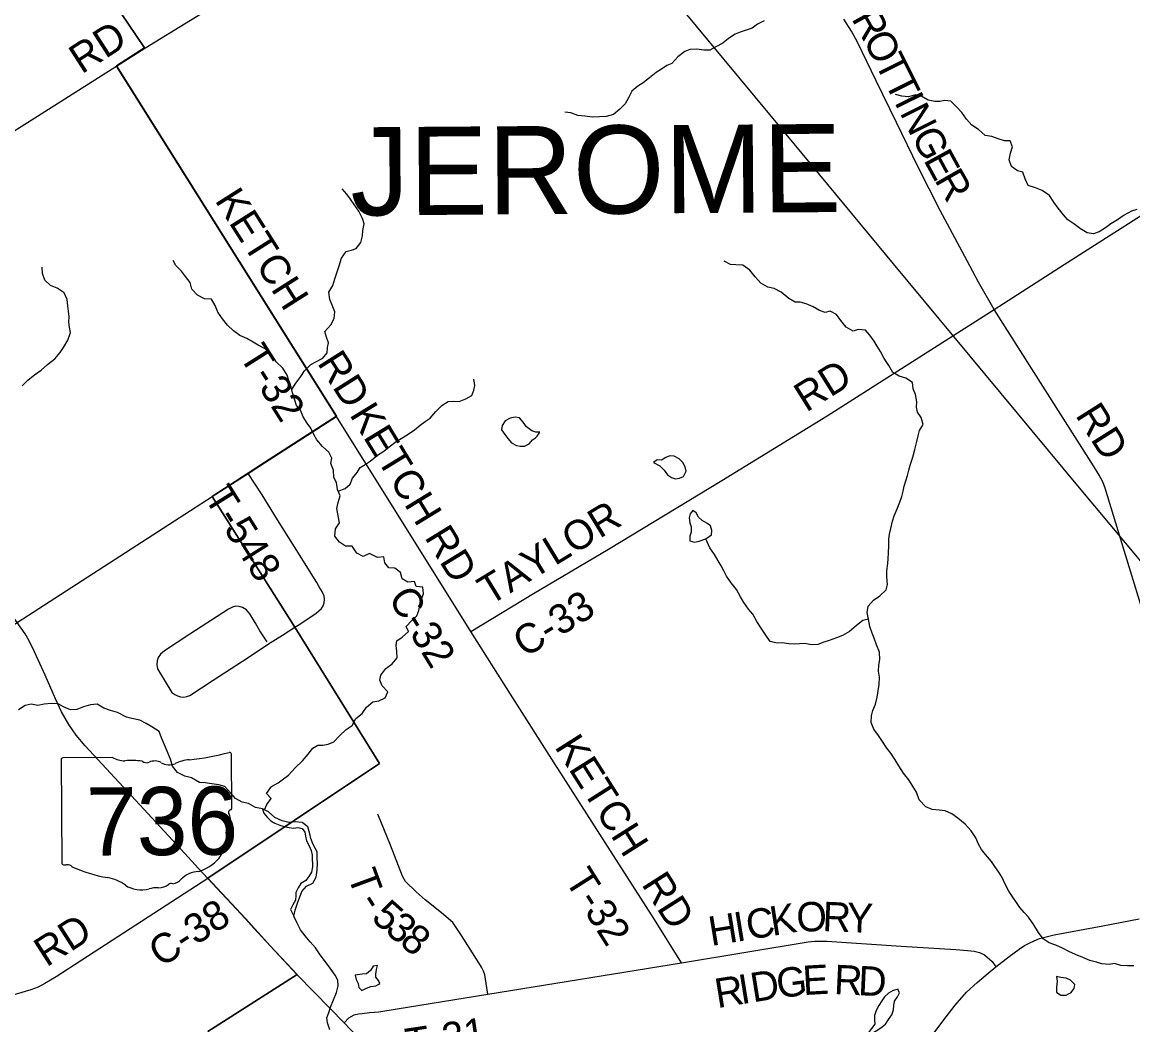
# Model space of a CAD drawing. Extents: x 114843 to 284848, y 317643 to 566895.
# Drawn here: x 122583 to 133928, y 449771 to 460005 of the extents above; entities that cross this region are included whole.
import ezdxf

# ---------------------------------------------------------------- set-up
doc = ezdxf.new("R2010")
doc.units = 0
for name, color, linetype in [('GM_X_County_Road', 7, 'Continuous'), ('GM_X_County_Road_Text', 7, 'Continuous'), ('GM_X_Minor_Lake', 7, 'Continuous'), ('GM_X_Minor_River', 7, 'Continuous'), ('GM_X_Rail_Line', 7, 'Continuous'), ('GM_X_State_Location', 7, 'Continuous'), ('GM_X_State_Route', 7, 'Continuous'), ('GM_X_State_Shield', 7, 'Continuous'), ('GM_X_Township', 7, 'Continuous'), ('GM_X_Township_Road', 7, 'Continuous'), ('GM_X_Township_Road_Text', 7, 'Continuous'), ('GM_X_Township_Text', 7, 'Continuous'), ('GM_X_US_Route', 7, 'Continuous')]:
    doc.layers.add(name, color=color, linetype=linetype)

msp = doc.modelspace()

# ---------------------------------------------------------------- linework, layer by layer
at = {"layer": 'GM_X_County_Road'}
for p, q in [((119922, 457268), (123503, 459530)), ((127165, 453787), (125795, 455981))]:
    msp.add_line(p, q, dxfattribs=at)
for points in [[(123503, 459530), (123547, 459558), (123835, 459740), (124769, 460317), (125852, 460988), (126885, 461624), (127403, 461928), (128041, 462305), (128800, 462760), (129060, 462921)], [(127165, 453787), (127806, 454172), (128572, 454626), (129729, 455328), (130805, 455988), (132510, 457074), (133226, 457531), (134315, 458226), (134761, 458512), (135424, 458946), (136182, 459448), (137071, 460040)], [(134087, 453804), (133840, 454613), (133647, 455248), (133620, 455313), (133584, 455383), (133526, 455477), (133168, 456038), (132510, 457074), (132352, 457352), (132237, 457571), (131960, 458084), (131737, 458524), (131513, 458982), (131306, 459407), (131114, 459802), (131053, 459913), (130977, 460037)], [(116865, 450191), (119055, 451622), (120275, 452411), (121363, 453112), (122533, 453877), (124525, 455162), (124893, 455400), (125060, 455508), (125795, 455981)], [(124481, 451264), (123193, 450430), (122929, 450259), (122814, 450192), (122745, 450154), (122672, 450126), (122520, 450083), (122291, 450023), (122223, 450000), (122163, 449980), (122102, 449952), (122051, 449925), (121544, 449630)]]:
    msp.add_lwpolyline(points, dxfattribs=at)
at = {"layer": 'GM_X_Minor_Lake'}
for points in [[(127826, 455764), (127844, 455779), (127872, 455821), (127830, 455821), (127788, 455833), (127736, 455875), (127702, 455923), (127662, 455965), (127620, 455975), (127568, 455963), (127518, 455937), (127486, 455887), (127478, 455845)], [(127478, 455845), (127512, 455797), (127545, 455757), (127581, 455713), (127633, 455683), (127671, 455677), (127713, 455677), (127761, 455701), (127795, 455741), (127826, 455764)], [(129349, 455387), (129365, 455422), (129355, 455466), (129332, 455512), (129294, 455547), (129242, 455577), (129200, 455579), (129158, 455561), (129115, 455535), (129071, 455537), (129033, 455510)], [(129033, 455510), (129097, 455477), (129141, 455431), (129175, 455384), (129215, 455356), (129255, 455344), (129299, 455352), (129339, 455368), (129349, 455387)], [(129566, 454732), (129626, 454773), (129628, 454817), (129613, 454865), (129575, 454893), (129529, 454919), (129491, 454953), (129469, 454997), (129435, 455022), (129419, 455003)], [(129419, 455003), (129407, 454988), (129395, 454947), (129403, 454895), (129416, 454855), (129416, 454799), (129404, 454757), (129404, 454711), (129450, 454699), (129500, 454709), (129566, 454732)], [(125037, 451976), (125050, 451930), (125086, 451890), (125122, 451853), (125164, 451829), (125216, 451809), (125260, 451795), (125310, 451783), (125356, 451777), (125402, 451783), (125442, 451773), (125472, 451737), (125478, 451695), (125488, 451649), (125514, 451597), (125536, 451550), (125544, 451502), (125546, 451456), (125550, 451416), (125550, 451382), (125538, 451328), (125510, 451284), (125479, 451244), (125431, 451212), (125403, 451170), (125379, 451120), (125377, 451090), (125375, 451044), (125349, 450996), (125325, 450948), (125357, 450878)], [(125357, 450878), (125371, 450942), (125395, 451012), (125417, 451068), (125439, 451130), (125489, 451186), (125551, 451216), (125586, 451276), (125598, 451348), (125600, 451420), (125596, 451472), (125596, 451536), (125556, 451611), (125532, 451671), (125522, 451721), (125502, 451791), (125442, 451835), (125372, 451841), (125308, 451835), (125238, 451851), (125164, 451887), (125099, 451946), (125037, 451976)], [(126219, 450183), (126236, 450191), (126224, 450221), (126194, 450257), (126194, 450287), (126204, 450334), (126212, 450374), (126168, 450370), (126142, 450324), (126100, 450292), (126056, 450288), (125986, 450276)], [(125986, 450276), (125996, 450234), (126014, 450192), (126022, 450151), (126054, 450119), (126100, 450145), (126146, 450161), (126194, 450169), (126219, 450183)], [(133150, 450265), (133156, 450215), (133148, 450153), (133150, 450105), (133192, 450074), (133248, 450072), (133277, 450089)], [(133277, 450089), (133294, 450098), (133330, 450140), (133336, 450182), (133290, 450225), (133246, 450245), (133194, 450253), (133150, 450265)], [(131535, 450121), (131531, 450133), (131479, 450119), (131431, 450093), (131393, 450055), (131365, 450015), (131333, 449967), (131305, 449917), (131289, 449866), (131291, 449822), (131293, 449776), (131259, 449734), (131228, 449692), (131210, 449650)], [(131210, 449650), (131264, 449684), (131305, 449710), (131353, 449738), (131401, 449778), (131433, 449824), (131467, 449872), (131485, 449924), (131487, 449968), (131493, 450010), (131523, 450056), (131543, 450097), (131535, 450121)]]:
    msp.add_lwpolyline(points, dxfattribs=at)
at = {"layer": 'GM_X_Minor_River'}
for points in [[(130163, 460019), (130093, 459987), (130041, 459945), (129987, 459929), (129917, 459905), (129865, 459885), (129799, 459839), (129739, 459791), (129669, 459753), (129607, 459719), (129545, 459719), (129475, 459729), (129403, 459727), (129351, 459707), (129282, 459653), (129218, 459585), (129168, 459565), (129114, 459527), (129060, 459493), (128990, 459439), (128926, 459385), (128872, 459353), (128810, 459301), (128776, 459233), (128741, 459173), (128689, 459119), (128623, 459063), (128547, 459043), (128479, 459041), (128405, 459037), (128329, 459047), (128259, 459053), (128189, 459082), (128125, 459088)], [(133969, 458093), (133915, 458077), (133841, 458035), (133773, 457987), (133705, 457947), (133649, 457907), (133583, 457865), (133528, 457845), (133462, 457855), (133393, 457897), (133327, 457946), (133263, 457988), (133219, 458040), (133167, 458106), (133121, 458170), (133077, 458236), (133003, 458289), (132933, 458313), (132859, 458339), (132829, 458407), (132803, 458475), (132749, 458487), (132689, 458531), (132664, 458599), (132678, 458670), (132700, 458734), (132674, 458794), (132618, 458796), (132554, 458816), (132488, 458838), (132420, 458850), (132352, 458910), (132284, 458956), (132230, 459017), (132182, 459085), (132132, 459139), (132070, 459201), (132008, 459205), (131958, 459195), (131906, 459197), (131838, 459209), (131774, 459248), (131708, 459264), (131638, 459244), (131568, 459252), (131504, 459266)], [(125337, 456256), (125378, 456321), (125428, 456389), (125468, 456447), (125530, 456511), (125584, 456539), (125654, 456575), (125700, 456631), (125701, 456683), (125711, 456733), (125687, 456799), (125675, 456849), (125737, 456915), (125769, 456981), (125777, 457049), (125749, 457117), (125725, 457176), (125716, 457250), (125758, 457316), (125778, 457386), (125796, 457448), (125820, 457518), (125844, 457596), (125894, 457664), (125946, 457678), (125996, 457694), (126044, 457758), (126059, 457826), (126063, 457878), (126077, 457946), (126059, 458002), (126021, 458077), (125973, 458145), (125937, 458199), (125901, 458249), (125853, 458303)], [(124553, 457113), (124517, 457177), (124445, 457181), (124373, 457219), (124315, 457279), (124299, 457348), (124251, 457408), (124210, 457464), (124154, 457522), (124124, 457572)], [(131243, 453837), (131227, 453911), (131214, 453980), (131224, 454044), (131278, 454104), (131344, 454150), (131408, 454212), (131422, 454264), (131416, 454342), (131414, 454404), (131426, 454480), (131430, 454530), (131433, 454586), (131435, 454664), (131435, 454727), (131443, 454779), (131457, 454837), (131473, 454913), (131491, 454967), (131521, 455037), (131547, 455105), (131570, 455165), (131582, 455219), (131592, 455269), (131608, 455323), (131628, 455379), (131640, 455432), (131658, 455494), (131682, 455564), (131702, 455644), (131720, 455712), (131737, 455784), (131749, 455836), (131785, 455900), (131765, 455970), (131727, 456024), (131717, 456075), (131721, 456131), (131709, 456205), (131683, 456263), (131677, 456329), (131610, 456373), (131540, 456391), (131476, 456431), (131436, 456500), (131388, 456572), (131352, 456644), (131316, 456698), (131286, 456748), (131240, 456810), (131196, 456860), (131122, 456867), (131072, 456853), (131000, 456893), (130946, 456959), (130902, 457021), (130836, 457055), (130784, 457043), (130728, 457063), (130662, 457099), (130593, 457132), (130529, 457146), (130479, 457146), (130413, 457184), (130335, 457248), (130265, 457286), (130201, 457300), (130127, 457343), (130071, 457405), (130015, 457473), (129945, 457525), (129873, 457529), (129819, 457533), (129755, 457565)], [(122583, 456292), (122645, 456356), (122709, 456404), (122778, 456454), (122842, 456512), (122918, 456568), (122970, 456632), (123004, 456686), (123048, 456760), (123076, 456838), (123068, 456892), (123060, 456945), (123062, 456997), (123057, 457055), (123049, 457111), (123041, 457175), (123011, 457243), (122939, 457291), (122871, 457317), (122813, 457371), (122791, 457440), (122787, 457504)], [(125059, 451965), (125081, 452018), (125127, 452080), (125079, 452132), (125131, 452202), (125197, 452240), (125251, 452282), (125305, 452320), (125373, 452394), (125445, 452466), (125506, 452532), (125552, 452594), (125604, 452626), (125654, 452626), (125710, 452634), (125766, 452658), (125824, 452720), (125892, 452784), (125954, 452826), (125992, 452896), (126056, 452950), (126101, 453012), (126165, 453068), (126227, 453078), (126291, 453108), (126319, 453170), (126259, 453232), (126237, 453287), (126245, 453339), (126297, 453409), (126361, 453457), (126413, 453517), (126410, 453585), (126404, 453641), (126410, 453691), (126464, 453729), (126530, 453785), (126504, 453835), (126560, 453895), (126616, 453945), (126634, 453999), (126646, 454053), (126654, 454103), (126683, 454171), (126677, 454238), (126609, 454244), (126589, 454296), (126523, 454288), (126465, 454324), (126447, 454388), (126391, 454432), (126327, 454436), (126287, 454488), (126279, 454547), (126211, 454541), (126131, 454581), (126067, 454551), (126001, 454585), (125953, 454655), (125887, 454657), (125823, 454699), (125777, 454760), (125783, 454832), (125826, 454896), (125810, 454966), (125798, 455040), (125810, 455102), (125830, 455170), (125804, 455236), (125794, 455306), (125768, 455357), (125764, 455431), (125737, 455499), (125747, 455555), (125715, 455615), (125651, 455673), (125593, 455743), (125563, 455796), (125531, 455862), (125495, 455912), (125455, 455978), (125425, 456044), (125385, 456094), (125364, 456158), (125346, 456223), (125332, 456279), (125308, 456347), (125290, 456401), (125246, 456475), (125178, 456539), (125134, 456609), (125064, 456670), (124994, 456708), (124942, 456738), (124877, 456776), (124805, 456808), (124741, 456854), (124679, 456912), (124629, 456977), (124583, 457045), (124553, 457113)], [(125811, 455218), (125882, 455244), (125934, 455288), (125956, 455352), (126004, 455408), (126035, 455460), (126087, 455490), (126137, 455526), (126211, 455584), (126279, 455628), (126331, 455670), (126403, 455726), (126453, 455756), (126515, 455792), (126589, 455844), (126647, 455892), (126700, 455928), (126750, 455962), (126810, 456032), (126870, 456094), (126936, 456132), (126986, 456138), (127048, 456132), (127114, 456160), (127176, 456196), (127198, 456248), (127206, 456298), (127196, 456362)], [(131227, 453911), (131171, 453897), (131105, 453847), (131035, 453785), (130963, 453743), (130901, 453722), (130827, 453694), (130773, 453678), (130711, 453654), (130645, 453650), (130579, 453664), (130523, 453660), (130471, 453656), (130415, 453660), (130345, 453670), (130295, 453668), (130223, 453682), (130179, 453748), (130131, 453819), (130087, 453889), (130047, 453961), (130003, 454013), (129955, 454081), (129919, 454139), (129880, 454214), (129824, 454282), (129776, 454350), (129752, 454404), (129724, 454456), (129692, 454508), (129656, 454571), (129608, 454639), (129566, 454732)], [(133940, 450372), (133872, 450372), (133806, 450376), (133742, 450396), (133688, 450386), (133612, 450394), (133556, 450411), (133488, 450427), (133416, 450459), (133342, 450489), (133274, 450517), (133210, 450551), (133142, 450583), (133074, 450606), (133013, 450648), (132965, 450712), (132917, 450792), (132863, 450868), (132817, 450918), (132775, 450968), (132739, 451019), (132703, 451073), (132661, 451133), (132619, 451213), (132593, 451273), (132558, 451329), (132518, 451388), (132486, 451438), (132422, 451510), (132384, 451560), (132352, 451616), (132324, 451678), (132278, 451750), (132214, 451817), (132140, 451879), (132078, 451925), (132012, 451953), (131950, 451961), (131880, 451969), (131812, 451995), (131746, 452068), (131717, 452144), (131685, 452200), (131639, 452270), (131587, 452338), (131537, 452413), (131499, 452475), (131455, 452545), (131417, 452595), (131371, 452663), (131329, 452725), (131284, 452789), (131254, 452856), (131260, 452926), (131274, 452980), (131298, 453042), (131318, 453116), (131326, 453178), (131336, 453246), (131340, 453320), (131331, 453380), (131333, 453441), (131343, 453501), (131339, 453575), (131309, 453649), (131287, 453717), (131265, 453769), (131243, 453837)], [(123004, 453018), (122952, 453046), (122878, 453052), (122808, 453043), (122742, 453029), (122674, 453043), (122612, 453031), (122546, 452985)], [(125727, 449719), (125701, 449789), (125695, 449841), (125715, 449897), (125733, 449949), (125764, 450024), (125794, 450100), (125810, 450168), (125808, 450226), (125780, 450276), (125730, 450348), (125682, 450414), (125626, 450483), (125578, 450555), (125524, 450617), (125473, 450677), (125425, 450741), (125387, 450813), (125357, 450878), (125371, 450942), (125395, 451012), (125417, 451068), (125439, 451130), (125489, 451186), (125551, 451216), (125586, 451276), (125598, 451348), (125600, 451420), (125596, 451472), (125596, 451536), (125556, 451611), (125532, 451671), (125522, 451721), (125502, 451791), (125442, 451835), (125372, 451841), (125308, 451835), (125238, 451851), (125164, 451887), (125099, 451946), (125037, 451976), (124965, 451988), (124895, 452030), (124831, 452042), (124763, 452080), (124715, 452134), (124653, 452203), (124591, 452219), (124521, 452231), (124451, 452239), (124393, 452245), (124313, 452291), (124245, 452307), (124171, 452346), (124117, 452410), (124097, 452482), (124037, 452630), (124006, 452700), (123984, 452766), (123908, 452813), (123850, 452847), (123784, 452881), (123704, 452897), (123650, 452911), (123558, 452959), (123486, 452978), (123416, 453002), (123350, 453044), (123280, 453038), (123210, 453018), (123142, 452988), (123078, 452986), (123004, 453018)]]:
    msp.add_lwpolyline(points, dxfattribs=at)
at = {"layer": 'GM_X_Rail_Line'}
msp.add_lwpolyline([(138183, 449466), (136987, 450906), (136046, 452039), (135244, 453008), (134166, 454316), (133384, 455251), (132101, 456798), (131484, 457539), (130386, 458864), (129755, 459626), (128906, 460649), (127697, 462105), (125636, 464591), (123883, 466703), (122754, 468064), (121680, 469357), (121113, 470043), (118437, 473269), (117495, 474413), (115816, 476427), (114843, 477600)], dxfattribs=at)
at = {"layer": 'GM_X_State_Route'}
for points in [[(123616, 452198), (123225, 452619), (123134, 452727), (123058, 452836), (122985, 452965), (122922, 453099), (122817, 453341), (122710, 453577), (122654, 453690), (122613, 453761), (122533, 453877), (122469, 453961)], [(124481, 451264), (124385, 451367), (124246, 451520), (123616, 452198)], [(124951, 450757), (124864, 450851), (124481, 451264)], [(125872, 449792), (125728, 449936), (125392, 450282), (125120, 450572), (124951, 450757)], [(126446, 449008), (126391, 449094), (126281, 449272), (126183, 449415), (126098, 449541), (126002, 449654), (125872, 449792)]]:
    msp.add_lwpolyline(points, dxfattribs=at)
at = {"layer": 'GM_X_State_Shield'}
for p, q in [((124725, 451981), (124721, 452534)), ((122981, 452477), (122988, 451421)), ((123507, 452499), (122998, 452496)), ((124724, 451982), (124725, 451981))]:
    msp.add_line(p, q, dxfattribs=at)
for centre, major_axis, ratio, start_param, end_param in [((124091, 453944), (1845, 13), 0.800001, 4.814396, 5.042371), ((124701, 452536), (19.4, 0.1), 0.8, 6.141152, 7.989035), ((123001, 452480), (20.2, 0.1), 0.8, 1.712693, 3.28349), ((123628, 452623), (196, 1), 0.8, 4.042523, 4.731795), ((123698, 451907), (702, 5), 0.8, 1.404758, 1.657858), ((123853, 452491), (56.4, 0.4), 0.8, 3.836095, 5.185415), ((123937, 452370), (117, 1), 0.8, 0.950623, 2.079405), ((124087, 452538), (141, 1), 0.8, 4.081561, 5.145723), ((124339, 452183), (371, 3), 0.8, 1.699011, 2.107814), ((124720, 451941), (30, 0.2), 0.8, 1.883978, 3.671073), ((124704, 451979), (20.7, 0.1), 0.8, 5.05454, 6.418171), ((124530, 451870), (180, 1), 0.8, 5.934695, 6.695948), ((124210, 451676), (462, 3), 0.8, 5.101753, 6.440018), ((124796, 451751), (131, 1), 0.8, 2.387724, 3.262537), ((123008, 451419), (20.3, 0.1), 0.8, 3.00124, 4.508301), ((123011, 451527), (155, 1), 0.8, 4.665946, 4.897461), ((123044, 451360), (56, 0.4), 0.8, 0.519207, 1.627899), ((123743, 452315), (1333, 10), 0.800001, 4.195996, 4.488959), ((124409, 451134), (253, 2), 0.8, 1.647645, 2.488433), ((123356, 450949), (417, 3), 0.8, 0.823519, 1.323588), ((123804, 451360), (265, 2), 0.8, 4.026481, 4.996735), ((123959, 450996), (217, 2), 0.8, 1.495662, 1.94098), ((123977, 451282), (141, 1), 0.8, 4.691044, 5.507374), ((124105, 451181), (39.7, 0.3), 0.8, 1.147584, 2.315152), ((124087, 451326), (149, 1), 0.8, 4.937069, 5.64225)]:
    msp.add_ellipse(centre, major_axis=major_axis, ratio=ratio, start_param=start_param, end_param=end_param, dxfattribs=at)
at = {"layer": 'GM_X_Township'}
for points in [[(119245, 466519), (123833, 459743), (123546, 459560), (125794, 455984), (125059, 455511), (124892, 455403), (124524, 455165), (125367, 453831), (126234, 452438), (124479, 451266), (124863, 450854), (125119, 450574), (125391, 450284), (124481, 449701)], [(124481, 449701), (125391, 450284), (125119, 450574), (124863, 450854), (124479, 451266), (126234, 452438), (125367, 453831), (124524, 455165), (124892, 455403), (125059, 455511), (125794, 455984), (123546, 459560), (123833, 459743), (119245, 466519)]]:
    msp.add_lwpolyline(points, dxfattribs=at)
at = {"layer": 'GM_X_Township_Road'}
for p, q in [((125795, 455981), (123547, 459558)), ((127165, 453787), (125795, 455981))]:
    msp.add_line(p, q, dxfattribs=at)
for points in [[(125403, 453851), (125552, 453949), (125587, 453973), (125615, 453995), (125639, 454021), (125657, 454048), (125668, 454079), (125672, 454117), (125668, 454145), (125651, 454188), (125618, 454242), (125593, 454285), (125364, 454650), (125192, 454925), (125035, 455179), (124893, 455400)], [(125087, 453679), (125012, 453791), (124967, 453872), (124910, 453966), (124874, 454008), (124833, 454032), (124801, 454039), (124764, 454043), (124730, 454033), (124690, 454013), (124296, 453757), (124036, 453589), (123995, 453554), (123973, 453521), (123963, 453485), (123959, 453449), (123967, 453405), (124042, 453275), (124113, 453164), (124143, 453142), (124169, 453130), (124202, 453118), (124234, 453116), (124265, 453122), (124297, 453132), (124535, 453288), (124834, 453483), (124962, 453567), (125098, 453661), (125242, 453749), (125369, 453828), (125403, 453851)], [(128042, 452406), (127570, 453147), (127165, 453787)], [(129318, 450403), (129042, 450846), (128537, 451630), (128053, 452388), (128042, 452406)], [(127339, 450084), (127317, 450237), (127309, 450279), (127297, 450319), (127276, 450359), (127249, 450404), (127069, 450683), (126982, 450813), (126867, 450913), (126701, 451045), (126607, 451127), (126498, 451233), (126467, 451288), (126344, 451603), (126217, 451919)], [(126412, 449934), (127339, 450084), (129318, 450403), (130613, 450617), (130681, 450624), (130803, 450623), (131563, 450572), (132119, 450538)], [(132119, 450538), (132239, 450530), (132308, 450523), (132361, 450508), (132413, 450485), (132491, 450417), (132529, 450363)], [(125872, 449792), (125920, 449843), (125974, 449873), (126019, 449882), (126056, 449885), (126132, 449896), (126226, 449904), (126412, 449934)]]:
    msp.add_lwpolyline(points, dxfattribs=at)
at = {"layer": 'GM_X_US_Route'}
msp.add_lwpolyline([(131817, 449578), (131989, 449807), (132112, 449972), (132230, 450105), (132339, 450201), (132449, 450298), (132529, 450363), (132666, 450467), (132767, 450543), (132821, 450580), (132870, 450605), (132921, 450628), (132976, 450650), (133044, 450667), (133124, 450688), (133623, 450781), (133992, 450852)], dxfattribs=at)

# ---------------------------------------------------------------- texts
at = {"layer": 'GM_X_County_Road_Text'}
for s, rotation, p in [('R', 298.9961, (131049, 460043)), ('RD', 32.771, (123190, 459471)), ('O', 297.1229, (131167, 459829)), ('T', 296.4415, (131287, 459595)), ('T', 296.432, (131387, 459394)), ('I', 296.4317, (131487, 459193)), ('N', 296.437, (131542, 459083)), ('G', 296.9532, (131661, 458844)), ('E', 298.6293, (131785, 458600)), ('R', 299.8044, (131896, 458397)), ('RD', 31.9569, (130592, 456018)), ('KETCH', 301.4099, (125921, 456001)), ('RD', 302.3103, (133335, 455994)), ('TAYLOR', 31.3751, (127358, 454045)), ('RD', 301.6287, (126687, 454748)), ('C-32', 301.4341, (126315, 454130)), ('C-33', 31.4348, (127717, 453513)), ('C-38', 32.6718, (124001, 450350)), ('RD', 32.7308, (122832, 450354))]:
    msp.add_text(s, height=300, rotation=rotation, dxfattribs=at).set_placement(p)
at = {"layer": 'GM_X_State_Location'}
for s, p in [('s', (123836, 451885)), ('r', (123836, 451885)), ('736', (123483, 451810))]:
    msp.add_text(s, height=1, rotation=0.411, dxfattribs=at).set_placement(p)
at = {"layer": 'GM_X_State_Shield'}
msp.add_text('736', height=696.1, rotation=0.411, dxfattribs=at).set_placement((123238, 451497))
at = {"layer": 'GM_X_Township_Road_Text'}
for s, rotation, p in [('KETCH', 302.3295, (124545, 458188)), ('T-32', 302.3412, (124793, 456598)), ('RD', 302.3116, (125591, 456528)), ('T-548', 302.0378, (124436, 455156)), ('KETCH', 302.3952, (128015, 452609)), ('T', 290.2719, (125903, 451295)), ('T-32', 302.3431, (128119, 451249)), ('RD', 302.4689, (128903, 451206)), ('-', 302.4545, (126012, 451022)), ('5', 318.4298, (126137, 450849)), ('C', 9.3704, (130003, 450637)), ('K', 9.2842, (130246, 450677)), ('O', 2.0143, (130496, 450719)), ('R', 357.6313, (130754, 450728)), ('Y', 357.7034, (131001, 450718)), ('3', 318.8954, (126277, 450725)), ('H', 9.3723, (129621, 450574)), ('I', 9.3692, (129881, 450617)), ('8', 321.0218, (126425, 450596)), ('G', 7.2119, (130306, 450040)), ('E', 3.2475, (130563, 450073)), ('R', 357.3009, (130871, 450085)), ('D', 357.3009, (131117, 450073)), ('R', 9.1941, (129684, 449940)), ('I', 9.1941, (129927, 449979)), ('D', 9.1941, (130048, 449999)), ('T-31', 8.5421, (126522, 449431))]:
    msp.add_text(s, height=300, rotation=rotation, dxfattribs=at).set_placement(p)
at = {"layer": 'GM_X_Township_Text'}
msp.add_text('JEROME', height=900, rotation=0.411, dxfattribs=at).set_placement((125938, 458032))

doc.saveas('drawing.dxf')
